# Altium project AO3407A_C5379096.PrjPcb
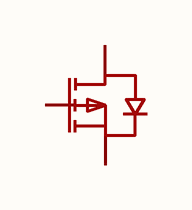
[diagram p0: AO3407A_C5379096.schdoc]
1 sheet, 1 parts. Net scope: global (net labels, ports and power ports of the same name join across sheets).

## Sheet AO3407A_C5379096.schdoc
size 127 x 101 mm

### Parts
Q?  ao3407a_c5379096  [SOT-23-3_L2.9-W1.6-P1.90-LS2.8-BR]  (value not drawn)

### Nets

Not connected (* = marked no-connect by the designer): Q? 1(G) 2(S) 3(D)

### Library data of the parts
Q? = ao3407a_c5379096: 数量:1个P沟道;漏源电压(Vdss):30V;连续漏极电流(Id):4.2A;导通电阻(RDS(on)):45mΩ@10V；60mΩ@4.5V;耗散功率(Pd):1.56W;阈值电压(Vgs(th)):1.5V;; Manufacturer: MSKSEMI(美森科); AddInBom: yes; ModelId: 89cb27a44ab2466697082bb9fd73a7d0; ModelName: SOT-23-3L_L2.9-W1.6-H1.1-LS2.8-P0.95; ModelTransform: 114.173,110.236,0,90,0,0,0,0,0; Number: 1个P沟道; Drain to Source Voltage: 30V; Current - Continuous Drain(Id): 4.2A; Pd - Power Dissipation: 1.56W; Gate Threshold Voltage (Vgs(th)): 1.5V; Gate Charge(Qg): 5.1nC@4.5V; Input Capacitance(Ciss): 560pF; Reverse Transfer Capacitance (Crss@Vds): 40pF; Output Capacitance(Coss): 55pF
